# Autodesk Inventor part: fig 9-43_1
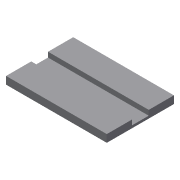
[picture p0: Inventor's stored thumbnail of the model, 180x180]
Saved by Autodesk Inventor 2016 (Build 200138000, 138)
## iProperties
Created: 2013-03
Part Number: fig 9-43_1
Material: Generic
Document SubType Name: Modeling
Designer: CADCIM
Density: 1 g/cm^3
Appearance: Default
Author: CADCIM
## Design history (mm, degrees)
sketch "Sketch1"
  geometry: L1 (-12.966, 10)-(17.034, 10); L2 (17.034, 10)-(17.034, -10); L3 (17.034, -10)-(-12.966, -10); L4 (-12.966, -10)-(-12.966, 10); 1 further point
  constraints: 8 end point, 2 parallel, 1 horizontal, 1 perpendicular
  dimensions: "d0" = 30 distance of L1.start L1.end; "d2" = 20 distance of L1.end L2.end
extrude "Extrusion1" new body sketch "Sketch1" distance "d3" = 2.25; taper "d4" = 0 deg
sketch "Sketch2"
  geometry: L1 (-12.966, 10)-(-12.966, -10) reference; L2 (-12.966, 2.498)-(87.034, 2.498); L3 (87.034, 2.498)-(87.034, -2.502); L4 (87.034, -2.502)-(-12.966, -2.502); L5 (-12.966, -2.502)-(-12.966, 2.498); 1 further point
  constraints: 8 end point, 2 parallel, 1 horizontal, 1 perpendicular, 1 point on line
  dimensions: "d5" = 5 distance of L2.end L3.end; "d7" = 100 distance of L2.start L2.end
extrude "Extrusion2" cut sketch "Sketch2" distance "d8" = 1.5; taper "d9" = 0 deg
body "Solid1"
